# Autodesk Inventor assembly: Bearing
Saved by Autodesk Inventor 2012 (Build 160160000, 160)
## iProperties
Created: 2011-01
Part Number: Bearing
Document SubType Name: Assembly
Designer: Beta-8540w
ClientObjectVersion: 1
Author: Beta-8540w
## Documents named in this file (2)
- C:\Users\VMuser\Desktop\Inventor 2012 Essentials\Assemblies\Chapter 8\Design Accelerators\Bearing c8-02.iam
- C:\Users\VMuser\Desktop\Inventor 2012 Essentials\Content Center Files\en-US\SKF B - angular contact\SKF B7204 BE.ipt
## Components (1 placed, 1 different names)
1. SKF B- Angular contact SKF B7204 BE:1
